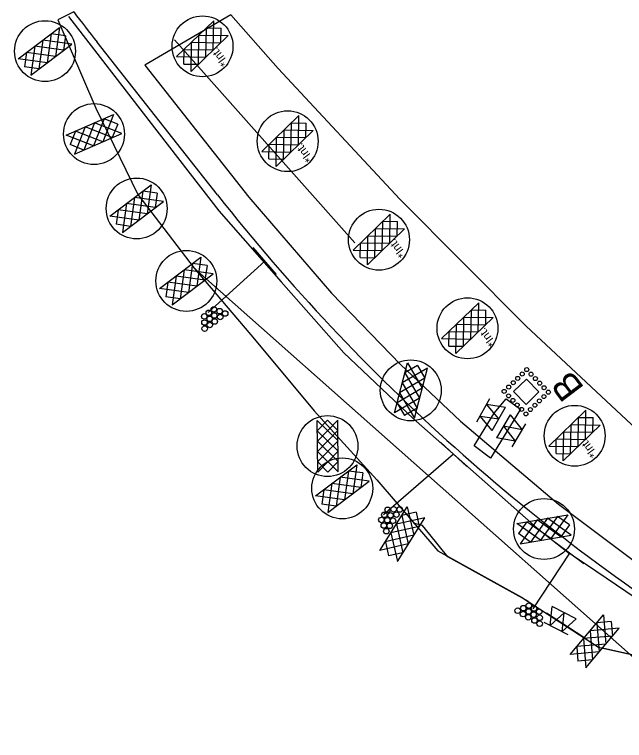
# Model space of a CAD drawing. Extents: x 400935 to 481562, y 415700 to 505362.
# Drawn here: x 476339.4 to 476680.8, y 500513.5 to 500919.6 of the extents above; entities that cross this region are included whole.
import ezdxf

# ---------------------------------------------------------------- set-up
doc = ezdxf.new("R2010")
doc.units = 0
for name, color, linetype in [('Drain Terminator Final CELL', 7, 'Continuous'), ('Earth Berm for Slope Drains Final', 7, 'Continuous'), ('Excelsior Wattle Line Style Final', 7, 'Continuous'), ('Label B Final CELL', 7, 'Continuous'), ('Matting on Slope Note Final CELL', 7, 'Continuous'), ('Old_Level_2', 7, 'Continuous'), ('Rock Inlet Sediment Trap Type B Final CELL', 7, 'Continuous'), ('Rock Silt Check Type A Both CELL', 7, 'Continuous'), ('Rock Silt Check Type A with Matting and PAM CG CELL', 7, 'Continuous'), ('Rock Silt Check Type A with Matting and PAM Final CELL', 7, 'Continuous'), ('Scratch_Level_4', 7, 'Continuous'), ('Slope Drain Final', 7, 'Continuous'), ('Slope Drain Inlet Final CELL', 7, 'Continuous'), ('Special Sediment Control Fence Section CG CELL', 7, 'Continuous'), ('Special Sediment Control Fence Section Final CELL', 7, 'Continuous'), ('Temporary Silt Fence Both', 7, 'Continuous'), ('Temporary Silt Fence CG', 7, 'Continuous'), ('Temporary Silt Fence Final', 7, 'Continuous')]:
    doc.layers.add(name, color=color, linetype=linetype)

msp = doc.modelspace()

# ---------------------------------------------------------------- linework, layer by layer
at = {"layer": 'Drain Terminator Final CELL'}
for centre in [(476448.21, 500752.73), (476450.97, 500754.7), (476454.21, 500753.67), (476457.3, 500752.36), (476445.63, 500750.73), (476448.61, 500749.35), (476451.27, 500751.24), (476451.48, 500747.89), (476454.53, 500750.39), (476445.73, 500747.3), (476445.83, 500743.87), (476448.71, 500745.92), (476548.27, 500642.55), (476551.65, 500642.79), (476555.01, 500642.73), (476546.42, 500639.7), (476549.82, 500639.45), (476553.17, 500639.87), (476544.77, 500636.89), (476548.05, 500636.71), (476551.26, 500636.42), (476546.13, 500633.74), (476547.5, 500630.59), (476549.41, 500633.56), (476621.05, 500586.08), (476624.17, 500587.51), (476627.17, 500585.65), (476627.29, 500588.93), (476630.13, 500587.33), (476633.02, 500585.55), (476624.05, 500584.22), (476626.94, 500582.44), (476629.95, 500583.93), (476633.33, 500582.16), (476630.44, 500580.59), (476633.33, 500578.81)]:
    msp.add_circle(centre, 1.55, dxfattribs=at)
at = {"layer": 'Earth Berm for Slope Drains Final'}
for points in [[(476369.64, 500918.54), (476414.67, 500860.36), (476453.74, 500809.88), (476488.71, 500770.16), (476523.68, 500730.45), (476562.55, 500693.54), (476607.4, 500653.97), (476631.99, 500632.28), (476650.05, 500618.16)], [(476738.89, 500557.95), (476698.94, 500585.02), (476659, 500612.09), (476650.05, 500618.16)]]:
    msp.add_lwpolyline(points, dxfattribs=at)
at = {"layer": 'Excelsior Wattle Line Style Final'}
msp.add_line((476685.75, 500559.92), (476440.04, 500777.65), dxfattribs=at)
at = {"layer": 'Matting on Slope Note Final CELL'}
for p, q in [((476372.57, 500921.11), (476363.61, 500916.7)), ((476363.61, 500916.7), (476384.86, 500867.22)), ((476453.04, 500818.71), (476385.69, 500904.17)), ((476384.86, 500867.22), (476408.41, 500819.03)), ((476408.41, 500819.03), (476440.04, 500777.65)), ((476440.04, 500777.65), (476473.74, 500738.02)), ((476473.74, 500738.02), (476507.13, 500697.93)), ((476507.13, 500697.93), (476542.22, 500659.35)), ((476542.22, 500659.35), (476576.42, 500619.66)), ((476576.42, 500619.66), (476623.23, 500593.63)), ((476623.23, 500593.63), (476666.18, 500565.67)), ((476666.18, 500565.67), (476722.02, 500553.15))]:
    msp.add_line(p, q, dxfattribs=at)
for centre, radius, start, end in [((477416.95, 501716.88), 1313, 217.30549, 218.24077), ((477327.21, 501507.62), 1113, 218.24077, 238.24455)]:
    msp.add_arc(centre, radius, start, end, dxfattribs=at)
at = {"layer": 'Old_Level_2'}
for p, q in [((476450.96, 500916.15), (476430.18, 500896.06)), ((476450.69, 500899.82), (476450.96, 500916.15)), ((476446.52, 500895.79), (476446.83, 500912.15)), ((476446.83, 500912.15), (476455, 500911.99)), ((476454.86, 500903.92), (476455, 500911.99)), ((476458.99, 500907.84), (476438.21, 500887.76)), ((476442.39, 500891.78), (476442.66, 500908.12)), ((476442.66, 500908.12), (476458.99, 500907.84)), ((476438.21, 500887.76), (476438.49, 500904.09)), ((476438.49, 500904.09), (476454.86, 500903.85)), ((476434.21, 500891.88), (476434.35, 500900.09)), ((476434.35, 500900.09), (476450.69, 500899.82)), ((476430.18, 500896.06), (476446.52, 500895.79)), ((476434.21, 500891.88), (476442.39, 500891.78)), ((476498.59, 500863.08), (476477.81, 500842.99)), ((476498.32, 500846.74), (476498.59, 500863.08)), ((476494.15, 500842.71), (476494.46, 500859.08)), ((476494.46, 500859.08), (476502.63, 500858.91)), ((476502.49, 500850.85), (476502.63, 500858.91)), ((476506.62, 500854.77), (476485.84, 500834.69)), ((476490.02, 500838.71), (476490.29, 500855.05)), ((476490.29, 500855.05), (476506.62, 500854.77)), ((476485.84, 500834.69), (476486.12, 500851.02)), ((476486.12, 500851.02), (476502.49, 500850.77)), ((476481.84, 500838.81), (476481.98, 500847.02)), ((476481.98, 500847.02), (476498.32, 500846.74)), ((476477.81, 500842.99), (476494.15, 500842.71)), ((476481.84, 500838.81), (476490.02, 500838.71)), ((476549.7, 500807.97), (476528.92, 500787.88)), ((476549.42, 500791.64), (476549.7, 500807.97)), ((476545.25, 500787.61), (476545.57, 500803.97)), ((476545.57, 500803.97), (476553.74, 500803.81)), ((476553.6, 500795.74), (476553.74, 500803.81)), ((476557.73, 500799.66), (476536.95, 500779.58)), ((476541.13, 500783.6), (476541.4, 500799.94)), ((476541.4, 500799.94), (476557.73, 500799.66)), ((476536.95, 500779.58), (476537.23, 500795.91)), ((476537.23, 500795.91), (476553.59, 500795.67)), ((476532.94, 500783.7), (476533.09, 500791.91)), ((476533.09, 500791.91), (476549.42, 500791.64)), ((476528.92, 500787.88), (476545.25, 500787.61)), ((476532.94, 500783.7), (476541.13, 500783.6)), ((476599.25, 500758.41), (476578.47, 500738.33)), ((476598.97, 500742.08), (476599.25, 500758.41)), ((476594.8, 500738.05), (476595.12, 500754.42)), ((476595.12, 500754.42), (476603.29, 500754.25)), ((476603.15, 500746.18), (476603.29, 500754.25)), ((476607.28, 500750.11), (476586.5, 500730.02)), ((476590.68, 500734.04), (476590.95, 500750.39)), ((476590.95, 500750.39), (476607.28, 500750.11)), ((476586.5, 500730.02), (476586.78, 500746.35)), ((476586.78, 500746.35), (476603.15, 500746.11)), ((476582.49, 500734.15), (476582.64, 500742.36)), ((476582.64, 500742.36), (476598.97, 500742.08)), ((476578.47, 500738.33), (476594.8, 500738.05)), ((476582.49, 500734.15), (476590.68, 500734.04)), ((476659.24, 500698.25), (476638.46, 500678.16)), ((476658.97, 500681.92), (476659.24, 500698.25)), ((476654.8, 500677.88), (476655.11, 500694.25)), ((476655.11, 500694.25), (476663.28, 500694.09)), ((476663.14, 500686.02), (476663.28, 500694.09)), ((476667.27, 500689.94), (476646.49, 500669.86)), ((476650.67, 500673.88), (476650.94, 500690.22)), ((476650.94, 500690.22), (476667.27, 500689.94)), ((476646.49, 500669.86), (476646.77, 500686.19)), ((476646.77, 500686.19), (476663.14, 500685.95)), ((476642.49, 500673.98), (476642.63, 500682.19)), ((476642.63, 500682.19), (476658.97, 500681.92)), ((476638.46, 500678.16), (476654.8, 500677.88)), ((476642.49, 500673.98), (476650.67, 500673.88))]:
    msp.add_line(p, q, dxfattribs=at)
for centre in [(476444.65, 500901.83), (476492.28, 500848.76), (476543.38, 500793.65), (476592.93, 500744.1), (476652.93, 500683.93)]:
    msp.add_circle(centre, 17.04, dxfattribs=at)
at = {"layer": 'Rock Inlet Sediment Trap Type B Final CELL'}
msp.add_lwpolyline([(476625.71, 500701.52), (476618.77, 500708.72), (476625.97, 500715.66), (476632.9, 500708.45)], close=True, dxfattribs=at)
for centre in [(476626.06, 500720.95), (476621.02, 500716.09), (476623.54, 500718.52), (476628.49, 500718.43), (476630.92, 500715.91), (476618.5, 500713.66), (476633.35, 500713.39), (476613.46, 500708.8), (476615.98, 500711.23), (476635.78, 500710.87), (476638.2, 500708.35), (476615.89, 500706.28), (476618.32, 500703.76), (476633.16, 500703.49), (476635.68, 500705.92), (476620.75, 500701.24), (476630.64, 500701.06), (476623.17, 500698.72), (476625.6, 500696.2), (476628.12, 500698.63)]:
    msp.add_circle(centre, 1.12, dxfattribs=at)
at = {"layer": 'Rock Silt Check Type A Both CELL'}
for p, q in [((476543.89, 500619.8), (476559.25, 500644.28)), ((476559.25, 500644.28), (476562.9, 500628.36)), ((476564.13, 500641.24), (476556.16, 500639.38)), ((476564.13, 500641.24), (476565.96, 500633.23)), ((476569.04, 500638.14), (476553.12, 500634.5)), ((476553.68, 500613.66), (476569.04, 500638.14)), ((476556.16, 500639.38), (476559.82, 500623.45)), ((476565.96, 500633.23), (476550.03, 500629.58)), ((476553.12, 500634.5), (476556.73, 500618.53)), ((476562.9, 500628.36), (476546.95, 500624.67)), ((476550.03, 500629.58), (476553.68, 500613.66)), ((476559.82, 500623.45), (476543.89, 500619.8)), ((476546.97, 500624.6), (476548.76, 500616.73)), ((476556.73, 500618.53), (476548.76, 500616.73)), ((476650.35, 500561.63), (476668.99, 500583.72)), ((476668.99, 500583.72), (476670.37, 500567.45)), ((476673.39, 500580.03), (476665.24, 500579.3)), ((476665.24, 500579.3), (476666.63, 500563.01)), ((476673.39, 500580.03), (476674.08, 500571.84)), ((476659.18, 500554.19), (476677.82, 500576.28)), ((476677.82, 500576.28), (476661.54, 500574.9)), ((476661.54, 500574.9), (476662.89, 500558.58)), ((476674.08, 500571.84), (476657.8, 500570.46)), ((476657.8, 500570.46), (476659.18, 500554.19)), ((476670.37, 500567.45), (476654.06, 500566.03)), ((476666.63, 500563.01), (476650.35, 500561.63)), ((476654.07, 500565.96), (476654.74, 500557.92)), ((476662.89, 500558.58), (476654.74, 500557.92))]:
    msp.add_line(p, q, dxfattribs=at)
at = {"layer": 'Rock Silt Check Type A with Matting and PAM CG CELL'}
for p, q in [((476552.06, 500696.74), (476559.35, 500724.71)), ((476559.35, 500724.71), (476567.61, 500710.62)), ((476570.52, 500721.8), (476556.44, 500713.53)), ((476564.91, 500723.28), (476557.87, 500719.1)), ((476563.24, 500693.83), (476570.52, 500721.8)), ((476564.91, 500723.28), (476569.06, 500716.19)), ((476557.87, 500719.1), (476566.15, 500705.01)), ((476569.06, 500716.19), (476554.97, 500707.92)), ((476556.44, 500713.53), (476564.69, 500699.4)), ((476567.61, 500710.62), (476553.51, 500702.31)), ((476566.15, 500705.01), (476552.06, 500696.74)), ((476554.97, 500707.92), (476563.24, 500693.83)), ((476553.55, 500702.25), (476557.62, 500695.28)), ((476564.69, 500699.4), (476557.62, 500695.28)), ((476509.09, 500663.63), (476508.8, 500692.53)), ((476508.8, 500692.53), (476520.47, 500681.1)), ((476514.55, 500692.6), (476508.85, 500686.73)), ((476520.35, 500692.65), (476508.92, 500680.98)), ((476514.55, 500692.6), (476520.41, 500686.85)), ((476520.64, 500663.75), (476520.35, 500692.65)), ((476508.85, 500686.73), (476520.53, 500675.3)), ((476520.41, 500686.85), (476508.98, 500675.18)), ((476508.92, 500680.98), (476520.59, 500669.5)), ((476520.47, 500681.1), (476509.04, 500669.38)), ((476508.98, 500675.18), (476520.64, 500663.75)), ((476520.53, 500675.3), (476509.09, 500663.63)), ((476509.09, 500669.33), (476514.84, 500663.68)), ((476520.59, 500669.5), (476514.84, 500663.68)), ((476620.52, 500634.93), (476649, 500639.8)), ((476649, 500639.8), (476639.57, 500626.47)), ((476626.14, 500635.84), (476621.48, 500629.26)), ((476631.9, 500636.88), (476622.47, 500623.54)), ((476639.57, 500626.47), (476626.18, 500635.9)), ((476637.62, 500637.85), (476628.13, 500624.51)), ((476645.24, 500627.44), (476631.9, 500636.88)), ((476643.28, 500638.84), (476633.85, 500625.49)), ((476650.95, 500628.42), (476637.62, 500637.85)), ((476649.99, 500634.14), (476643.28, 500638.84)), ((476633.85, 500625.49), (476620.52, 500634.93)), ((476649.99, 500634.14), (476645.24, 500627.44)), ((476628.13, 500624.51), (476621.48, 500629.26)), ((476622.47, 500623.54), (476650.95, 500628.42))]:
    msp.add_line(p, q, dxfattribs=at)
for centre in [(476561.18, 500709.35), (476514.59, 500678.18), (476635.75, 500631.81)]:
    msp.add_circle(centre, 17.04, dxfattribs=at)
at = {"layer": 'Rock Silt Check Type A with Matting and PAM Final CELL'}
for p, q in [((476341.52, 500894.9), (476364.56, 500912.34)), ((476364.56, 500912.34), (476362.32, 500896.16)), ((476359.93, 500908.85), (476357.7, 500892.66)), ((476368.04, 500907.76), (476359.93, 500908.85)), ((476368.04, 500907.76), (476366.91, 500899.63)), ((476355.35, 500905.37), (476353.07, 500889.16)), ((476371.53, 500903.13), (476355.35, 500905.37)), ((476348.49, 500885.69), (476371.53, 500903.13)), ((476350.73, 500901.87), (476348.49, 500885.69)), ((476366.91, 500899.63), (476350.73, 500901.87)), ((476346.09, 500898.3), (476344.98, 500890.3)), ((476362.32, 500896.16), (476346.1, 500898.37)), ((476357.7, 500892.66), (476341.52, 500894.9)), ((476353.07, 500889.16), (476344.98, 500890.3)), ((476368.38, 500852.13), (476394.89, 500863.65)), ((476394.89, 500863.65), (476388.9, 500848.46)), ((476384.29, 500859.05), (476378.26, 500843.83)), ((476389.56, 500861.35), (476383.58, 500846.14)), ((476399.49, 500853.06), (476384.29, 500859.05)), ((476397.19, 500858.38), (476389.56, 500861.35)), ((476378.97, 500856.74), (476372.99, 500841.54)), ((476394.17, 500850.75), (476378.97, 500856.74)), ((476397.19, 500858.38), (476394.17, 500850.75)), ((476383.58, 500846.14), (476368.38, 500852.13)), ((476373.63, 500854.36), (476370.66, 500846.85)), ((476372.99, 500841.54), (476399.49, 500853.06)), ((476388.9, 500848.46), (476373.65, 500854.42)), ((476378.26, 500843.83), (476370.66, 500846.85)), ((476392.82, 500806.87), (476415.87, 500824.31)), ((476415.87, 500824.31), (476413.63, 500808.13)), ((476411.24, 500820.82), (476409, 500804.63)), ((476419.35, 500819.74), (476411.24, 500820.82)), ((476419.35, 500819.74), (476418.21, 500811.6)), ((476399.8, 500797.66), (476422.84, 500815.11)), ((476406.66, 500817.34), (476404.38, 500801.13)), ((476422.84, 500815.11), (476406.66, 500817.34)), ((476397.4, 500810.27), (476396.29, 500802.28)), ((476413.63, 500808.13), (476397.41, 500810.34)), ((476402.03, 500813.84), (476399.8, 500797.66)), ((476418.21, 500811.6), (476402.03, 500813.84)), ((476409, 500804.63), (476392.82, 500806.87)), ((476404.38, 500801.13), (476396.29, 500802.28)), ((476420.63, 500766.35), (476443.68, 500783.8)), ((476443.68, 500783.8), (476441.44, 500767.62)), ((476439.05, 500780.31), (476436.81, 500764.12)), ((476447.16, 500779.22), (476439.05, 500780.31)), ((476447.16, 500779.22), (476446.02, 500771.09)), ((476427.61, 500757.15), (476450.65, 500774.59)), ((476434.47, 500776.83), (476432.19, 500760.62)), ((476450.65, 500774.59), (476434.47, 500776.83)), ((476425.21, 500769.76), (476424.1, 500761.76)), ((476441.44, 500767.62), (476425.22, 500769.83)), ((476429.84, 500773.33), (476427.61, 500757.15)), ((476446.02, 500771.09), (476429.84, 500773.33)), ((476436.81, 500764.12), (476420.63, 500766.35)), ((476432.19, 500760.62), (476424.1, 500761.76)), ((476507.87, 500650.28), (476530.92, 500667.73)), ((476526.28, 500664.24), (476524.05, 500648.05)), ((476534.4, 500663.15), (476526.28, 500664.24)), ((476530.92, 500667.73), (476528.68, 500651.55)), ((476521.71, 500660.76), (476519.43, 500644.54)), ((476537.89, 500658.52), (476521.71, 500660.76)), ((476534.4, 500663.15), (476533.26, 500655.02)), ((476514.84, 500641.07), (476537.89, 500658.52)), ((476517.08, 500657.25), (476514.84, 500641.07)), ((476533.26, 500655.02), (476517.08, 500657.25)), ((476512.45, 500653.68), (476511.33, 500645.69)), ((476528.68, 500651.55), (476512.46, 500653.75)), ((476524.05, 500648.05), (476507.87, 500650.28)), ((476519.43, 500644.54), (476511.33, 500645.69))]:
    msp.add_line(p, q, dxfattribs=at)
for centre in [(476356.48, 500899.14), (476383.92, 500852.73), (476407.79, 500811.12), (476435.6, 500770.6), (476522.84, 500654.53)]:
    msp.add_circle(centre, 17.04, dxfattribs=at)
at = {"layer": 'Scratch_Level_4'}
msp.add_line((476428.96, 500905.42), (476529.81, 500791.99), dxfattribs=at)
msp.add_lwpolyline([(476700.51, 500603.6), (476734.83, 500645.29), (476698.65, 500677.13), (476625.62, 500745.44), (476555.03, 500816.27), (476486.96, 500889.51), (476460.53, 500919.37), (476412.38, 500891.32), (476470.62, 500817.51), (476516.82, 500763.81), (476555.4, 500723.85), (476589.04, 500692.09), (476643.8, 500645.68), (476693.9, 500608.23)], close=True, dxfattribs=at)
at = {"layer": 'Slope Drain Final'}
for p, q in [((476479.55, 500781.72), (476447.76, 500752.97)), ((476585.12, 500673.61), (476545.93, 500639.75)), ((476649.99, 500618.26), (476629.52, 500587.11))]:
    msp.add_line(p, q, dxfattribs=at)
at = {"layer": 'Slope Drain Inlet Final CELL'}
for p, q in [((476486.11, 500774.17), (476472.98, 500789.27)), ((476592.49, 500666.86), (476577.74, 500680.36)), ((476658.02, 500612.3), (476641.96, 500624.22))]:
    msp.add_line(p, q, dxfattribs=at)
at = {"layer": 'Special Sediment Control Fence Section CG CELL'}
for p, q in [((476598.1, 500691.76), (476605.49, 500704.81)), ((476606.81, 500686.83), (476614.19, 500699.89)), ((476616.85, 500695.71), (476609.17, 500682.83)), ((476625.44, 500690.59), (476617.76, 500677.71))]:
    msp.add_line(p, q, dxfattribs=at)
for points in [[(476610.5, 500693.36), (476603.64, 500701.55), (476614.19, 500699.89)], [(476606.81, 500686.83), (476599.95, 500695.02), (476610.5, 500693.36)], [(476616.85, 500695.71), (476623.52, 500687.37), (476613.01, 500689.27)], [(476613.01, 500689.27), (476619.68, 500680.93), (476609.17, 500682.83)]]:
    msp.add_lwpolyline(points, dxfattribs=at)
at = {"layer": 'Special Sediment Control Fence Section Final CELL'}
for p, q in [((476653.71, 500581.6), (476640.33, 500588.37)), ((476649.2, 500572.67), (476635.81, 500579.45))]:
    msp.add_line(p, q, dxfattribs=at)
for points in [[(476647.02, 500584.98), (476639.16, 500577.75), (476640.33, 500588.37)], [(476653.71, 500581.6), (476645.85, 500574.37), (476647.02, 500584.98)]]:
    msp.add_lwpolyline(points, dxfattribs=at)
at = {"layer": 'Temporary Silt Fence Both'}
for points in [[(476627.08, 500591.16), (476581.88, 500616.29), (476571.87, 500628.74), (476567.84, 500633.67), (476562.57, 500635.11)], [(476788.67, 500513.49), (476767.9, 500529.47), (476722.02, 500553.15), (476668.42, 500565.17)]]:
    msp.add_lwpolyline(points, dxfattribs=at)
at = {"layer": 'Temporary Silt Fence CG'}
msp.add_lwpolyline([(476605.83, 500671.51), (476596.69, 500678.38), (476607.95, 500696.61), (476614.61, 500704.71), (476622.52, 500698.76)], close=True, dxfattribs=at)
at = {"layer": 'Temporary Silt Fence Final'}
msp.add_line((476658.1, 500571.03), (476637.06, 500584.68), dxfattribs=at)

# ---------------------------------------------------------------- texts
at = {"layer": 'Label B Final CELL'}
msp.add_text('B', height=15, rotation=127.1236, dxfattribs=at).set_placement((476658.66, 500710.71))
at = {"layer": 'Old_Level_2'}
for p in [(476459.41, 500892.78), (476506.74, 500839.21), (476558.86, 500785.73), (476609.21, 500736.01), (476665.94, 500673.95)]:
    msp.add_text('*Int.', height=4.746, rotation=127.1236, dxfattribs=at).set_placement(p)

doc.saveas('drawing.dxf')
